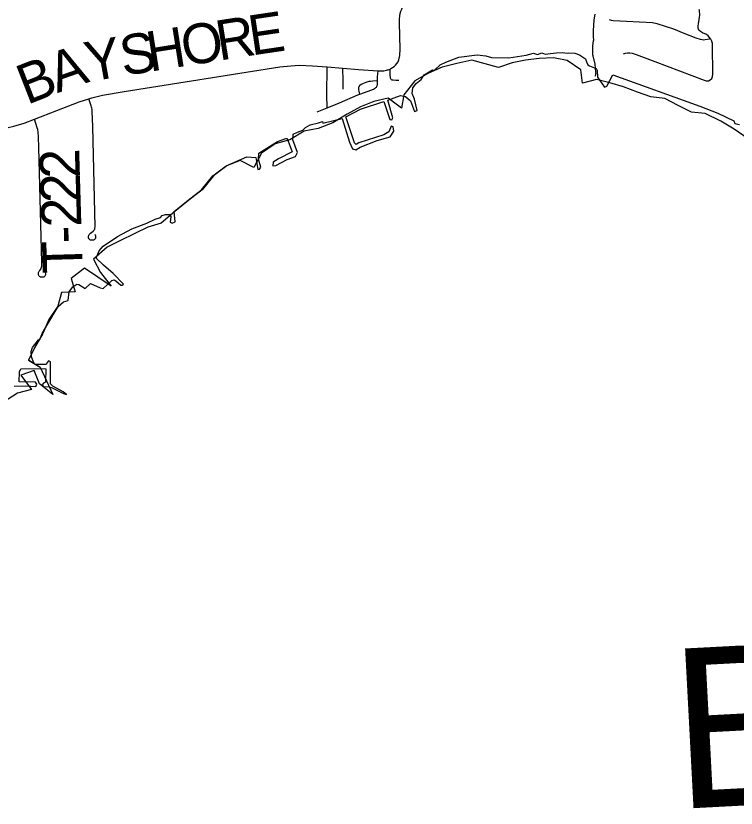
# Model space of a CAD drawing. Extents: x 63.4 to 97.4, y 0.4 to 22.4.
# Drawn here: x 69.704 to 70.728, y 14.849 to 15.976 of the extents above; entities that cross this region are included whole.
import ezdxf

# ---------------------------------------------------------------- set-up
doc = ezdxf.new("R2010")
doc.units = 0
for name, color, linetype in [('GM_X_County_Road', 7, 'Continuous'), ('GM_X_County_Road_Text', 7, 'Continuous'), ('GM_X_Major_Lake', 7, 'Continuous'), ('GM_X_Major_Lake_Text', 7, 'Continuous'), ('GM_X_Minor_River', 7, 'Continuous'), ('GM_X_Township_Road', 7, 'Continuous'), ('GM_X_Township_Road_Text', 7, 'Continuous'), ('SH_Cut_Line', 7, 'Continuous')]:
    doc.layers.add(name, color=color, linetype=linetype)

msp = doc.modelspace()

# ---------------------------------------------------------------- linework, layer by layer
at = {"layer": 'GM_X_County_Road'}
msp.add_line((70.1464, 15.9034), (70.1689, 15.9016), dxfattribs=at)
for points in [[(70.2361, 15.9004), (70.237, 15.9009), (70.2396, 15.9023), (70.2417, 15.904), (70.2439, 15.906), (70.2458, 15.9083), (70.2474, 15.9108), (70.2485, 15.9135), (70.2498, 15.9194), (70.2501, 15.9286), (70.2493, 15.966), (70.2494, 15.9712), (70.25, 15.9762), (70.2504, 15.9792), (70.2512, 15.9825), (70.2525, 15.9857), (70.2538, 15.9883), (70.2558, 15.9913), (70.2585, 15.9947)], [(69.7016, 15.4492), (69.7182, 15.4497), (69.7324, 15.449), (69.734, 15.4522), (69.7317, 15.4553), (69.7086, 15.4554), (69.7093, 15.47), (69.7111, 15.4739), (69.7441, 15.4744), (69.7466, 15.4739), (69.7461, 15.4551), (69.7431, 15.4535), (69.7415, 15.4512), (69.7431, 15.4486), (69.7506, 15.4491), (69.7558, 15.4471), (69.7715, 15.4392), (69.7762, 15.4376), (69.7712, 15.4415), (69.7564, 15.4492), (69.7532, 15.4525), (69.7533, 15.484), (69.7506, 15.4853), (69.7488, 15.4835), (69.7469, 15.4801), (69.7308, 15.4802), (69.7285, 15.4851), (69.7262, 15.4911), (69.7257, 15.4985), (69.7276, 15.5042), (69.736, 15.5155), (69.7384, 15.5169), (69.7414, 15.5245), (69.7495, 15.5378), (69.7641, 15.5628), (69.7716, 15.5694), (69.7782, 15.5713), (69.7799, 15.5834), (69.7849, 15.5906), (69.7908, 15.5946), (69.7936, 15.5941), (69.8027, 15.5884), (69.81, 15.5953), (69.824, 15.5894), (69.8281, 15.5884), (69.8405, 15.5995), (69.8437, 15.6005), (69.8459, 15.5994), (69.8532, 15.5932), (69.8553, 15.5931), (69.857, 15.5943), (69.8422, 15.6097), (69.8288, 15.6216), (69.818, 15.6313), (69.8226, 15.6416), (69.828, 15.6486), (69.8485, 15.6621), (69.8688, 15.6732), (69.8902, 15.681), (69.902, 15.687), (69.9095, 15.6893), (69.912, 15.6921), (69.9169, 15.6933), (69.9224, 15.6933), (69.9243, 15.6908), (69.9235, 15.6826), (69.9264, 15.6812), (69.9306, 15.6831), (69.9292, 15.6979), (69.9489, 15.7138), (69.9679, 15.7286), (69.9842, 15.7484), (70.0032, 15.7628), (70.0322, 15.7757), (70.045, 15.7744), (70.0482, 15.7575), (70.0504, 15.7578), (70.0522, 15.7609), (70.0491, 15.772), (70.0496, 15.7807), (70.0761, 15.7973), (70.0876, 15.8016), (70.0895, 15.8018), (70.0967, 15.7824), (70.0775, 15.7728), (70.0696, 15.7678), (70.0694, 15.7628), (70.0737, 15.763), (70.0898, 15.7719), (70.1013, 15.776), (70.1044, 15.7817), (70.0979, 15.7999), (70.0984, 15.8076), (70.1044, 15.8107), (70.112, 15.8136), (70.1159, 15.8172), (70.1226, 15.8208), (70.1343, 15.8239), (70.1401, 15.8256), (70.1403, 15.8232), (70.1677, 15.8301), (70.1784, 15.7963), (70.1825, 15.7867), (70.1871, 15.7855), (70.1933, 15.7894), (70.2177, 15.7985), (70.236, 15.8038), (70.2412, 15.8119), (70.2405, 15.8181), (70.2374, 15.8189), (70.2341, 15.8112), (70.2273, 15.8066), (70.1916, 15.7954), (70.1878, 15.7932), (70.1852, 15.7956), (70.1732, 15.8323), (70.1938, 15.8433), (70.2273, 15.8543), (70.2355, 15.8285), (70.2386, 15.828), (70.24, 15.8311), (70.2326, 15.856), (70.2506, 15.8627), (70.2578, 15.8613), (70.2652, 15.8553), (70.2707, 15.8402), (70.2746, 15.8412), (70.2707, 15.8577), (70.2676, 15.8656), (70.2681, 15.8735), (70.2729, 15.88), (70.2803, 15.8855), (70.2844, 15.8922), (70.2961, 15.8994), (70.2993, 15.8989), (70.3074, 15.9061), (70.3151, 15.9102), (70.3335, 15.9171), (70.3596, 15.9207), (70.3719, 15.9191), (70.38, 15.9169), (70.4047, 15.9164), (70.4296, 15.92), (70.4397, 15.9231), (70.4457, 15.921), (70.4519, 15.9234), (70.4565, 15.9214), (70.4639, 15.9224), (70.4725, 15.9234), (70.4812, 15.9238), (70.4876, 15.9231), (70.49, 15.9234), (70.4987, 15.9231), (70.5054, 15.9205), (70.514, 15.9147), (70.515, 15.9104), (70.5171, 15.9061), (70.5193, 15.9049), (70.5291, 15.9011), (70.5305, 15.8982), (70.5308, 15.8889), (70.5406, 15.8745), (70.5442, 15.8761), (70.5526, 15.8922), (70.6763, 15.8474), (70.7017, 15.8378), (70.7245, 15.8265), (70.7259, 15.8229), (70.7326, 15.8215)], [(69.8077, 15.8582), (69.812, 15.8596), (69.8272, 15.8632), (69.8578, 15.8686), (70.0792, 15.9033), (70.0947, 15.9051), (70.1072, 15.9059), (70.1259, 15.9051), (70.1464, 15.9034)], [(70.1689, 15.9016), (70.191, 15.8998), (70.2189, 15.8977)], [(70.2189, 15.8977), (70.225, 15.8978), (70.2273, 15.898), (70.229, 15.8983), (70.231, 15.8987), (70.2321, 15.8991), (70.2333, 15.8994), (70.2361, 15.9004)], [(69.7305, 15.8292), (69.7942, 15.8537), (69.8077, 15.8582)], [(69.6931, 15.8171), (69.701, 15.8189), (69.7158, 15.8236), (69.7305, 15.8292)]]:
    msp.add_lwpolyline(points, dxfattribs=at)
at = {"layer": 'GM_X_Major_Lake'}
for points in [[(70.7449, 15.8009), (70.7251, 15.8149), (70.7061, 15.8263), (70.6841, 15.8369), (70.6644, 15.8388), (70.6454, 15.8483), (70.6264, 15.8586), (70.6067, 15.8609), (70.5877, 15.8673), (70.568, 15.8749), (70.5486, 15.8806), (70.5293, 15.8855), (70.5096, 15.8802), (70.5073, 15.8992), (70.4875, 15.9125), (70.4682, 15.9163), (70.4481, 15.9155), (70.4284, 15.9129), (70.4094, 15.9091), (70.39, 15.9026), (70.371, 15.9079), (70.3521, 15.9129), (70.3308, 15.9083), (70.31, 15.903), (70.2906, 15.8946), (70.2712, 15.8836), (70.2553, 15.8638), (70.2523, 15.8445), (70.2333, 15.8589), (70.2128, 15.854), (70.1938, 15.8464), (70.1749, 15.8361), (70.1544, 15.8239), (70.1339, 15.8156), (70.1138, 15.8122), (70.0937, 15.7996), (70.0728, 15.7939), (70.0534, 15.7806), (70.0421, 15.7605), (70.0231, 15.7704), (70.0041, 15.7628), (69.9851, 15.7483), (69.9688, 15.7286), (69.9499, 15.7137), (69.9301, 15.6978), (69.9108, 15.6814), (69.8918, 15.6754), (69.8724, 15.6662), (69.8527, 15.6567), (69.8337, 15.6472), (69.8144, 15.6298), (69.8243, 15.6108), (69.8394, 15.5918), (69.8205, 15.6043), (69.8015, 15.6172), (69.7825, 15.6024), (69.7882, 15.5834), (69.7689, 15.5827), (69.7639, 15.5633), (69.7507, 15.5443), (69.7423, 15.5244), (69.7305, 15.5041), (69.7218, 15.4868)], [(70.7449, 15.8009), (70.7251, 15.8149), (70.7061, 15.8263), (70.6841, 15.8369), (70.6644, 15.8388), (70.6454, 15.8483), (70.6264, 15.8586), (70.6067, 15.8609), (70.5877, 15.8673), (70.568, 15.8749), (70.5486, 15.8806), (70.5293, 15.8855), (70.5096, 15.8802), (70.5073, 15.8992), (70.4875, 15.9125), (70.4682, 15.9163), (70.4481, 15.9155), (70.4284, 15.9129), (70.4094, 15.9091), (70.39, 15.9026), (70.371, 15.9079), (70.3521, 15.9129), (70.3308, 15.9083), (70.31, 15.903), (70.2906, 15.8946), (70.2712, 15.8836), (70.2553, 15.8638), (70.2523, 15.8445), (70.2333, 15.8589), (70.2128, 15.854), (70.1938, 15.8464), (70.1749, 15.8361), (70.1544, 15.8239), (70.1339, 15.8156), (70.1138, 15.8122), (70.0937, 15.7996), (70.0728, 15.7939), (70.0534, 15.7806), (70.0421, 15.7605), (70.0231, 15.7704), (70.0041, 15.7628), (69.9851, 15.7483), (69.9688, 15.7286), (69.9499, 15.7137), (69.9301, 15.6978), (69.9108, 15.6814), (69.8918, 15.6754), (69.8724, 15.6662), (69.8527, 15.6567), (69.8337, 15.6472), (69.8144, 15.6298), (69.8243, 15.6108), (69.8394, 15.5918), (69.8205, 15.6043), (69.8015, 15.6172), (69.7825, 15.6024), (69.7882, 15.5834), (69.7689, 15.5827), (69.7639, 15.5633), (69.7507, 15.5443), (69.7423, 15.5244), (69.7305, 15.5041), (69.7219, 15.4863)], [(69.7218, 15.4868), (69.7386, 15.4762), (69.7477, 15.4568), (69.7568, 15.4375), (69.7378, 15.4527), (69.7299, 15.4717), (69.7109, 15.4648), (69.7261, 15.4447), (69.7063, 15.4393), (69.6866, 15.4268), (69.6771, 15.4047), (69.6695, 15.3857), (69.6627, 15.3663), (69.654, 15.3458)], [(69.7219, 15.4863), (69.7386, 15.4762), (69.7477, 15.4568), (69.7568, 15.4375), (69.7378, 15.4527), (69.7299, 15.4717), (69.7109, 15.4648), (69.7261, 15.4447), (69.7063, 15.4393), (69.6866, 15.4268), (69.6771, 15.4047), (69.6695, 15.3857), (69.6627, 15.3663), (69.654, 15.3458)]]:
    msp.add_lwpolyline(points, dxfattribs=at)
at = {"layer": 'GM_X_Minor_River'}
msp.add_lwpolyline([(70.5277, 15.8904), (70.5285, 15.8922), (70.5285, 15.8938), (70.5289, 15.8941), (70.5285, 15.8957), (70.5282, 15.9014), (70.5276, 15.9074), (70.5247, 15.9189), (70.5244, 15.9204), (70.5244, 15.9215), (70.5242, 15.9333), (70.525, 15.9405), (70.5254, 15.942), (70.5251, 15.9455), (70.5252, 15.9546), (70.5262, 15.9701), (70.5275, 15.9785)], dxfattribs=at)
at = {"layer": 'GM_X_Township_Road'}
msp.add_line((70.1324, 15.8394), (70.1465, 15.8451), dxfattribs=at)
for points in [[(70.6912, 15.9438), (70.6902, 15.9452), (70.6881, 15.9475), (70.6856, 15.9493), (70.6799, 15.9519), (70.6772, 15.9535), (70.6751, 15.9557), (70.674, 15.9585), (70.6738, 15.9616), (70.6742, 15.9647), (70.6755, 15.9709), (70.6759, 15.974), (70.6761, 15.9771), (70.6757, 15.9837), (70.6756, 15.9848)], [(70.5472, 15.9706), (70.5503, 15.9698), (70.5533, 15.9694), (70.5626, 15.9687), (70.5999, 15.9671), (70.6092, 15.9663), (70.6153, 15.9651), (70.6272, 15.9615), (70.6389, 15.9575), (70.6534, 15.9514), (70.6708, 15.9447), (70.6767, 15.9428), (70.6797, 15.9422), (70.6822, 15.9421), (70.6841, 15.9423), (70.6901, 15.9435), (70.6912, 15.9438)], [(70.5676, 15.922), (70.5706, 15.9229), (70.5737, 15.9234), (70.5768, 15.9233), (70.5799, 15.9227), (70.5858, 15.9209), (70.6122, 15.9111), (70.6297, 15.9043), (70.6648, 15.8912), (70.6824, 15.8845), (70.6855, 15.8837), (70.6885, 15.8838), (70.6912, 15.8849), (70.6933, 15.8871), (70.6944, 15.8899), (70.6948, 15.893), (70.6945, 15.9337), (70.6941, 15.9368), (70.6933, 15.9398), (70.692, 15.9426), (70.6912, 15.9438)], [(70.1465, 15.8451), (70.1463, 15.8638), (70.1464, 15.9034)], [(70.1692, 15.8715), (70.1693, 15.8837), (70.1689, 15.9016)], [(70.2182, 15.884), (70.2183, 15.8893), (70.2185, 15.8932), (70.2189, 15.8977)], [(70.2483, 15.8839), (70.2464, 15.8839), (70.2442, 15.8839), (70.2404, 15.8843), (70.2391, 15.8846), (70.2382, 15.8851), (70.2375, 15.8857), (70.2371, 15.8863), (70.2367, 15.8874), (70.2365, 15.8884), (70.2364, 15.8894), (70.2363, 15.8902), (70.2362, 15.8921), (70.2361, 15.8952), (70.2361, 15.9004)], [(70.1928, 15.8646), (70.1924, 15.8665), (70.1919, 15.8688), (70.1916, 15.8707), (70.1915, 15.8719), (70.1915, 15.8729), (70.1916, 15.874), (70.1917, 15.875), (70.1923, 15.8762), (70.1928, 15.8769), (70.1932, 15.8774), (70.1949, 15.8786), (70.1961, 15.8793), (70.1971, 15.8798), (70.1994, 15.8808), (70.2022, 15.8819), (70.2061, 15.8831), (70.208, 15.8833), (70.2114, 15.8837), (70.2182, 15.884)], [(70.1928, 15.8646), (70.2048, 15.8691), (70.2125, 15.8719), (70.214, 15.8725), (70.2148, 15.873), (70.2159, 15.8739), (70.2166, 15.8747), (70.217, 15.8753), (70.2173, 15.876), (70.2176, 15.8769), (70.2179, 15.8777), (70.218, 15.8788), (70.2181, 15.8798), (70.2182, 15.884)], [(70.1465, 15.8451), (70.1643, 15.8523), (70.1901, 15.8636), (70.1928, 15.8646)], [(69.8162, 15.6654), (69.8166, 15.6647), (69.8171, 15.6633), (69.8174, 15.6624), (69.8174, 15.6613), (69.8173, 15.6603), (69.817, 15.6596), (69.8163, 15.6585), (69.8154, 15.6576), (69.8146, 15.6572), (69.8135, 15.657), (69.8124, 15.6568), (69.8111, 15.6569), (69.8101, 15.6572), (69.8092, 15.6577), (69.8086, 15.6582), (69.8078, 15.6589), (69.8075, 15.6598), (69.8073, 15.6606), (69.8072, 15.6618), (69.8074, 15.6627), (69.8076, 15.6636), (69.8079, 15.6643), (69.8084, 15.665), (69.8089, 15.6656), (69.8094, 15.6661), (69.8102, 15.6668), (69.812, 15.6683), (69.8141, 15.67), (69.8152, 15.6711), (69.8159, 15.672), (69.8161, 15.6726), (69.8164, 15.674), (69.8166, 15.6759), (69.8135, 15.8184), (69.8127, 15.8401), (69.8124, 15.843), (69.8122, 15.8445), (69.8117, 15.8463), (69.8111, 15.8479), (69.8077, 15.8582)], [(69.7445, 15.613), (69.7454, 15.6119), (69.7459, 15.6108), (69.7462, 15.6093), (69.7462, 15.6083), (69.746, 15.6076), (69.7457, 15.6067), (69.7452, 15.606), (69.7448, 15.6054), (69.7436, 15.6045), (69.743, 15.6044), (69.741, 15.6042), (69.7398, 15.6042), (69.739, 15.6045), (69.7384, 15.6048), (69.7377, 15.6052), (69.737, 15.606), (69.7365, 15.6069), (69.7362, 15.6077), (69.7361, 15.6085), (69.7361, 15.6097), (69.7362, 15.6103), (69.7364, 15.6111), (69.7369, 15.6121), (69.7373, 15.6127), (69.738, 15.6137), (69.7393, 15.6156), (69.7401, 15.617), (69.7405, 15.6187), (69.7407, 15.6202), (69.7409, 15.6233), (69.7409, 15.6254), (69.7367, 15.7889), (69.7361, 15.8039), (69.7356, 15.8107), (69.7351, 15.8142), (69.7344, 15.8168), (69.7305, 15.8292)]]:
    msp.add_lwpolyline(points, dxfattribs=at)
at = {"layer": 'SH_Cut_Line'}
msp.add_lwpolyline([(69.7016, 15.4492), (69.7182, 15.4497), (69.7324, 15.449), (69.734, 15.4522), (69.7317, 15.4553), (69.7086, 15.4554), (69.7093, 15.47), (69.7111, 15.4739), (69.7441, 15.4744), (69.7466, 15.4739), (69.7461, 15.4551), (69.7431, 15.4535), (69.7415, 15.4512), (69.7431, 15.4486), (69.7506, 15.4491), (69.7558, 15.4471), (69.7715, 15.4392), (69.7762, 15.4376), (69.7712, 15.4415), (69.7564, 15.4492), (69.7532, 15.4525), (69.7533, 15.484), (69.7506, 15.4853), (69.7488, 15.4835), (69.7469, 15.4801), (69.7308, 15.4802), (69.7285, 15.4851), (69.7262, 15.4911), (69.7257, 15.4985), (69.7276, 15.5042), (69.736, 15.5155), (69.7384, 15.5169), (69.7414, 15.5245), (69.7495, 15.5378), (69.7641, 15.5628), (69.7716, 15.5694), (69.7782, 15.5713), (69.7799, 15.5834), (69.7849, 15.5906), (69.7908, 15.5946), (69.7936, 15.5941), (69.8027, 15.5884), (69.81, 15.5953), (69.824, 15.5894), (69.8281, 15.5884), (69.8405, 15.5995), (69.8437, 15.6005), (69.8459, 15.5994), (69.8532, 15.5932), (69.8553, 15.5931), (69.857, 15.5943), (69.8422, 15.6097), (69.8288, 15.6216), (69.818, 15.6313), (69.8226, 15.6416), (69.828, 15.6486), (69.8485, 15.6621), (69.8688, 15.6732), (69.8902, 15.681), (69.902, 15.687), (69.9095, 15.6893), (69.912, 15.6921), (69.9169, 15.6933), (69.9224, 15.6933), (69.9243, 15.6908), (69.9235, 15.6826), (69.9264, 15.6812), (69.9306, 15.6831), (69.9292, 15.6979), (69.9489, 15.7138), (69.9679, 15.7286), (69.9842, 15.7484), (70.0032, 15.7628), (70.0322, 15.7757), (70.045, 15.7744), (70.0482, 15.7575), (70.0504, 15.7578), (70.0522, 15.7609), (70.0491, 15.772), (70.0496, 15.7807), (70.0761, 15.7973), (70.0876, 15.8016), (70.0895, 15.8018), (70.0967, 15.7824), (70.0775, 15.7728), (70.0696, 15.7678), (70.0694, 15.7628), (70.0737, 15.763), (70.0898, 15.7719), (70.1013, 15.776), (70.1044, 15.7817), (70.0979, 15.7999), (70.0984, 15.8076), (70.1044, 15.8107), (70.112, 15.8136), (70.1159, 15.8172), (70.1226, 15.8208), (70.1343, 15.8239), (70.1401, 15.8256), (70.1403, 15.8232), (70.1677, 15.8301), (70.1784, 15.7963), (70.1825, 15.7867), (70.1871, 15.7855), (70.1933, 15.7894), (70.2177, 15.7985), (70.236, 15.8038), (70.2412, 15.8119), (70.2405, 15.8181), (70.2374, 15.8189), (70.2341, 15.8112), (70.2273, 15.8066), (70.1916, 15.7954), (70.1878, 15.7932), (70.1852, 15.7956), (70.1732, 15.8323), (70.1938, 15.8433), (70.2273, 15.8543), (70.2355, 15.8285), (70.2386, 15.828), (70.24, 15.8311), (70.2326, 15.856), (70.2506, 15.8627), (70.2578, 15.8613), (70.2652, 15.8553), (70.2707, 15.8402), (70.2746, 15.8412), (70.2707, 15.8577), (70.2676, 15.8656), (70.2681, 15.8735), (70.2729, 15.88), (70.2803, 15.8855), (70.2844, 15.8922), (70.2961, 15.8994), (70.2993, 15.8989), (70.3074, 15.9061), (70.3151, 15.9102), (70.3335, 15.9171), (70.3596, 15.9207), (70.3719, 15.9191), (70.38, 15.9169), (70.4047, 15.9164), (70.4296, 15.92), (70.4397, 15.9231), (70.4457, 15.921), (70.4519, 15.9234), (70.4565, 15.9214), (70.4639, 15.9224), (70.4725, 15.9234), (70.4812, 15.9238), (70.4876, 15.9231), (70.49, 15.9234), (70.4987, 15.9231), (70.5054, 15.9205), (70.514, 15.9147), (70.515, 15.9104), (70.5171, 15.9061), (70.5193, 15.9049), (70.5291, 15.9011), (70.5305, 15.8982), (70.5308, 15.8889), (70.5406, 15.8745), (70.5442, 15.8761), (70.5526, 15.8922), (70.6763, 15.8474), (70.7017, 15.8378), (70.7245, 15.8265), (70.7259, 15.8229), (70.7326, 15.8215)], dxfattribs=at)

# ---------------------------------------------------------------- texts
at = {"layer": 'GM_X_County_Road_Text'}
for s, rotation, p in [('E', 8.4625, (70.0391, 15.9195)), ('O', 9.0024, (69.9437, 15.9044)), ('R', 8.9862, (69.9931, 15.9122)), ('H', 9.0042, (69.8944, 15.8965)), ('Y', 10.1475, (69.8076, 15.8818)), ('S', 9.0194, (69.8565, 15.8905)), ('A', 19.2546, (69.7627, 15.8659)), ('B', 21.393, (69.7198, 15.8491))]:
    msp.add_text(s, height=0.0568, rotation=rotation, dxfattribs=at).set_placement(p)
at = {"layer": 'GM_X_Major_Lake_Text'}
msp.add_text('B A Y', height=0.22741, rotation=3.0064, dxfattribs=at).set_placement((70.6424, 14.848))
at = {"layer": 'GM_X_Township_Road_Text'}
for s, rotation, p in [('2', 91.7358, (69.7952, 15.7457)), ('2', 91.6919, (69.7962, 15.711)), ('2', 91.6709, (69.7972, 15.6763)), ('-', 91.6643, (69.7979, 15.6531)), ('T', 91.6626, (69.7991, 15.6107))]:
    msp.add_text(s, height=0.0568, rotation=rotation, dxfattribs=at).set_placement(p)

doc.saveas('drawing.dxf')
